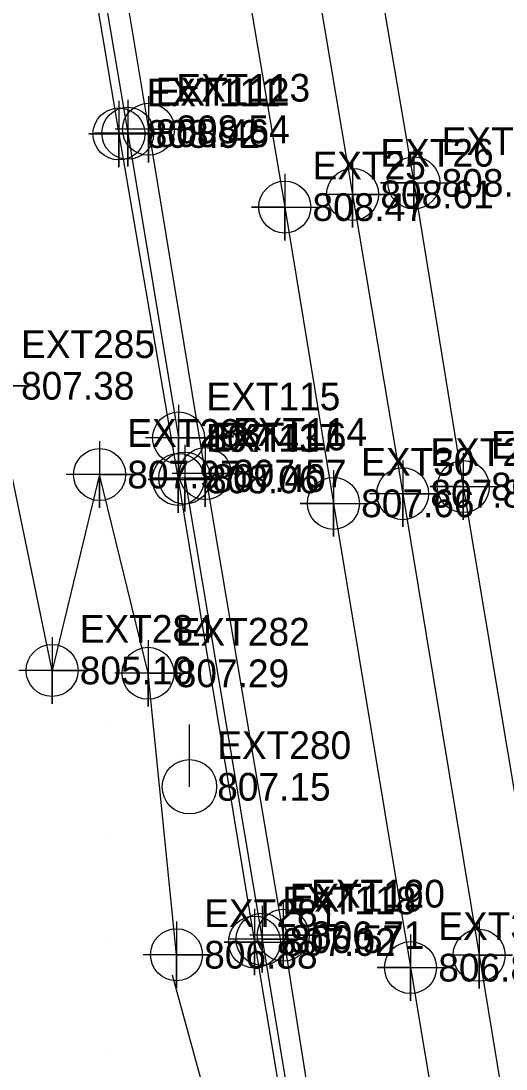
# Model space of a CAD drawing. Extents: x 1762120 to 1766775, y 709485 to 712965.
# Drawn here: x 1763802.3 to 1763846.1, y 712558.7 to 712653.2 of the extents above; entities that cross this region are included whole.
import ezdxf

# ---------------------------------------------------------------- set-up
doc = ezdxf.new("R2010")
doc.units = 0
for name, color, linetype in [('Exist DTM Breakline', 7, 'Continuous'), ('Exist DTM Breakline Cogo Elevation', 7, 'Continuous'), ('Exist DTM Breakline Cogo Number', 7, 'Continuous'), ('Exist DTM Breakline Cogo Point CELL', 7, 'Continuous'), ('Exist DTM Crownline', 7, 'Continuous'), ('Exist DTM Crownline Cogo Elevation', 7, 'Continuous'), ('Exist DTM Crownline Cogo Number', 7, 'Continuous'), ('Exist DTM Crownline Cogo Point CELL', 7, 'Continuous'), ('Exist DTM Drainline', 7, 'Continuous'), ('Exist DTM Drainline Cogo Elevation', 7, 'Continuous'), ('Exist DTM Drainline Cogo Number', 7, 'Continuous'), ('Exist DTM Drainline Cogo Point CELL', 7, 'Continuous'), ('Exist DTM QL2 LIDAR Elevation Point', 7, 'Continuous'), ('Exist Roads Curbs', 7, 'Continuous'), ('Exist Roads Curbs Cogo Elevation', 7, 'Continuous'), ('Exist Roads Curbs Cogo Number', 7, 'Continuous'), ('Exist Roads Curbs Cogo Point CELL', 7, 'Continuous'), ('Exist Roads EOP', 7, 'Continuous'), ('Exist Roads EOP Cogo Elevation', 7, 'Continuous'), ('Exist Roads EOP Cogo Number', 7, 'Continuous'), ('Exist Roads EOP Cogo Point CELL', 7, 'Continuous'), ('Exist Roads EOT', 7, 'Continuous'), ('Exist Roads EOT Cogo Elevation', 7, 'Continuous'), ('Exist Roads EOT Cogo Number', 7, 'Continuous'), ('Exist Roads EOT Cogo Point CELL', 7, 'Continuous'), ('Exist Utilities Power Pole CELL', 7, 'Continuous'), ('Exist Utilities Power Pole Cogo Elevation', 7, 'Continuous'), ('Exist Utilities Power Pole Cogo Number', 7, 'Continuous'), ('PH Exist DTM Breakline', 7, 'Continuous')]:
    doc.layers.add(name, color=color, linetype=linetype)

msp = doc.modelspace()

# ---------------------------------------------------------------- linework, layer by layer
at = {"layer": 'Exist DTM Breakline'}
msp.add_lwpolyline([(1763816.336, 712568.975), (1763813.77, 712594.344), (1763809.401, 712612.263), (1763805.117, 712594.603), (1763799.817, 712620.266), (1763789.401, 712652.954), (1763785.334, 712685.719)], dxfattribs=at)
at = {"layer": 'Exist DTM Breakline Cogo Point CELL'}
for points in [[(1763799.817, 712623.266), (1763799.817, 712617.266), (1763799.817, 712620.266), (1763802.817, 712620.266), (1763796.817, 712620.266)], [(1763809.401, 712615.263), (1763809.401, 712609.263), (1763809.401, 712612.263), (1763812.401, 712612.263), (1763806.401, 712612.263)], [(1763805.117, 712597.603), (1763805.117, 712591.603), (1763805.117, 712594.603), (1763808.117, 712594.603), (1763802.117, 712594.603)], [(1763813.77, 712597.344), (1763813.77, 712591.344), (1763813.77, 712594.344), (1763816.77, 712594.344), (1763810.77, 712594.344)], [(1763816.336, 712571.975), (1763816.336, 712565.975), (1763816.336, 712568.975), (1763819.336, 712568.975), (1763813.336, 712568.975)]]:
    msp.add_lwpolyline(points, dxfattribs=at)
for centre in [(1763809.401, 712612.263), (1763805.117, 712594.603), (1763813.77, 712594.344), (1763816.336, 712568.975)]:
    msp.add_circle(centre, 2.344, dxfattribs=at)
at = {"layer": 'Exist DTM Crownline'}
msp.add_line((1763843.626, 712568.925), (1763848.874, 712537.033), dxfattribs=at)
msp.add_lwpolyline([(1763783.92, 712926.058), (1763790.262, 712887.319), (1763795.183, 712859.532), (1763803.032, 712808.629), (1763808.926, 712776.275), (1763814.523, 712743.371), (1763820.27, 712708.85), (1763825.749, 712675.916), (1763832.222, 712637.522), (1763836.733, 712610.54), (1763843.626, 712568.925)], dxfattribs=at)
at = {"layer": 'Exist DTM Crownline Cogo Point CELL'}
for points in [[(1763832.222, 712640.522), (1763832.222, 712634.522), (1763832.222, 712637.522), (1763835.222, 712637.522), (1763829.222, 712637.522)], [(1763836.733, 712613.54), (1763836.733, 712607.54), (1763836.733, 712610.54), (1763839.733, 712610.54), (1763833.733, 712610.54)], [(1763843.626, 712571.925), (1763843.626, 712565.925), (1763843.626, 712568.925), (1763846.626, 712568.925), (1763840.626, 712568.925)]]:
    msp.add_lwpolyline(points, dxfattribs=at)
for centre in [(1763832.222, 712637.522), (1763836.733, 712610.54), (1763843.626, 712568.925)]:
    msp.add_circle(centre, 2.344, dxfattribs=at)
at = {"layer": 'Exist DTM Drainline'}
msp.add_line((1763817.077, 712611.946), (1763824.048, 712570.37), dxfattribs=at)
for points in [[(1763781.288, 712825.282), (1763786.304, 712795.661), (1763793.687, 712751.498), (1763799.331, 712717.754), (1763805.438, 712681.563), (1763811.952, 712643.035), (1763816.532, 712615.56)], [(1763824.048, 712570.37), (1763827.225, 712551.256), (1763833.688, 712512.933), (1763834.31, 712508.288)]]:
    msp.add_lwpolyline(points, dxfattribs=at)
at = {"layer": 'Exist DTM Drainline Cogo Point CELL'}
for points in [[(1763811.952, 712646.035), (1763811.952, 712640.035), (1763811.952, 712643.035), (1763814.952, 712643.035), (1763808.952, 712643.035)], [(1763816.532, 712618.56), (1763816.532, 712612.56), (1763816.532, 712615.56), (1763819.532, 712615.56), (1763813.532, 712615.56)], [(1763817.077, 712614.946), (1763817.077, 712608.946), (1763817.077, 712611.946), (1763820.077, 712611.946), (1763814.077, 712611.946)], [(1763824.048, 712573.37), (1763824.048, 712567.37), (1763824.048, 712570.37), (1763827.048, 712570.37), (1763821.048, 712570.37)]]:
    msp.add_lwpolyline(points, dxfattribs=at)
for centre in [(1763811.952, 712643.035), (1763816.532, 712615.56), (1763817.077, 712611.946), (1763824.048, 712570.37)]:
    msp.add_circle(centre, 2.344, dxfattribs=at)
at = {"layer": 'Exist DTM QL2 LIDAR Elevation Point'}
for p, q in [((1763810, 712620), (1763810, 712620)), ((1763810, 712590), (1763810, 712590)), ((1763810, 712580), (1763810, 712580)), ((1763810, 712570), (1763810, 712570)), ((1763810, 712560), (1763810, 712560))]:
    msp.add_line(p, q, dxfattribs=at)
at = {"layer": 'Exist Roads Curbs'}
for points in [[(1763764.468, 712921.993), (1763771.224, 712881.371), (1763777.799, 712842.52), (1763785.017, 712799.156), (1763793.002, 712751.297), (1763798.517, 712717.85), (1763798.751, 712716.41), (1763801.856, 712697.916), (1763802.154, 712696.936), (1763804.688, 712681.498), (1763811.149, 712642.967), (1763816.501, 712611.824), (1763823.372, 712570.121)], [(1763823.372, 712570.121), (1763826.523, 712551.26), (1763832.916, 712512.967), (1763833.683, 712508.175)]]:
    msp.add_lwpolyline(points, dxfattribs=at)
at = {"layer": 'Exist Roads Curbs Cogo Point CELL'}
for points in [[(1763811.149, 712645.967), (1763811.149, 712639.967), (1763811.149, 712642.967), (1763808.419, 712642.967), (1763814.149, 712642.967)], [(1763816.501, 712614.824), (1763816.501, 712608.824), (1763816.501, 712611.824), (1763813.771, 712611.824), (1763819.501, 712611.824)], [(1763823.372, 712573.121), (1763823.372, 712567.121), (1763823.372, 712570.121), (1763820.642, 712570.121), (1763826.372, 712570.121)]]:
    msp.add_lwpolyline(points, dxfattribs=at)
for centre in [(1763811.149, 712642.967), (1763816.501, 712611.824), (1763823.372, 712570.121)]:
    msp.add_circle(centre, 2.344, dxfattribs=at)
at = {"layer": 'Exist Roads EOP'}
for points in [[(1763767.083, 712922.223), (1763773.823, 712881.974), (1763780.335, 712842.895), (1763788.848, 712791.154), (1763795.539, 712751.806), (1763801.2, 712718.139), (1763807.385, 712682.013), (1763813.812, 712643.387), (1763818.936, 712612.35), (1763825.965, 712570.729)], [(1763825.965, 712570.729), (1763828.989, 712551.557), (1763835.435, 712513.335), (1763836.189, 712508.687)]]:
    msp.add_lwpolyline(points, dxfattribs=at)
at = {"layer": 'Exist Roads EOP Cogo Point CELL'}
for points in [[(1763813.812, 712646.387), (1763813.812, 712640.387), (1763813.812, 712643.387), (1763816.812, 712643.387), (1763810.812, 712643.387)], [(1763818.936, 712615.35), (1763818.936, 712609.35), (1763818.936, 712612.35), (1763821.936, 712612.35), (1763815.936, 712612.35)], [(1763825.965, 712573.729), (1763825.965, 712567.729), (1763825.965, 712570.729), (1763828.965, 712570.729), (1763822.965, 712570.729)]]:
    msp.add_lwpolyline(points, dxfattribs=at)
for centre in [(1763813.812, 712643.387), (1763818.936, 712612.35), (1763825.965, 712570.729)]:
    msp.add_circle(centre, 2.344, dxfattribs=at)
at = {"layer": 'Exist Roads EOT'}
for points in [[(1763789.832, 712926.884), (1763795.992, 712888.052), (1763800.75, 712859.942), (1763807.254, 712820.955), (1763816.86, 712762.721), (1763822.148, 712731.849), (1763825.695, 712709.767), (1763831.213, 712676.817), (1763837.744, 712638.56), (1763842.2, 712611.183), (1763849.139, 712569.759)], [(1763777.488, 712924.55), (1763781.487, 712903.204), (1763789.164, 712854.697), (1763797.205, 712808.308), (1763802.541, 712775.258), (1763808.303, 712742.168), (1763814.095, 712707.894), (1763819.559, 712674.99), (1763826.1, 712636.377), (1763830.485, 712609.669), (1763837.441, 712567.81)], [(1763837.441, 712567.81), (1763842.568, 712537.12), (1763847.598, 712508.586)]]:
    msp.add_lwpolyline(points, dxfattribs=at)
at = {"layer": 'Exist Roads EOT Cogo Point CELL'}
for points in [[(1763837.744, 712641.56), (1763837.744, 712635.56), (1763837.744, 712638.56), (1763834.744, 712638.56), (1763840.744, 712638.56)], [(1763826.1, 712639.377), (1763826.1, 712633.377), (1763826.1, 712636.377), (1763823.1, 712636.377), (1763829.1, 712636.377)], [(1763842.2, 712614.183), (1763842.2, 712608.183), (1763842.2, 712611.183), (1763839.2, 712611.183), (1763845.2, 712611.183)], [(1763830.485, 712612.669), (1763830.485, 712606.669), (1763830.485, 712609.669), (1763827.485, 712609.669), (1763833.485, 712609.669)], [(1763837.441, 712570.81), (1763837.441, 712564.81), (1763837.441, 712567.81), (1763834.441, 712567.81), (1763840.441, 712567.81)]]:
    msp.add_lwpolyline(points, dxfattribs=at)
for centre in [(1763837.744, 712638.56), (1763826.1, 712636.377), (1763842.2, 712611.183), (1763830.485, 712609.669), (1763837.441, 712567.81)]:
    msp.add_circle(centre, 2.344, dxfattribs=at)
at = {"layer": 'Exist Utilities Power Pole CELL'}
for q in [(1763817.508, 712589.739), (1763817.508, 712584.114)]:
    msp.add_line((1763817.508, 712584.114), q, dxfattribs=at)
msp.add_circle((1763817.508, 712584.114), 2.45, dxfattribs=at)
at = {"layer": 'PH Exist DTM Breakline'}
msp.add_lwpolyline([(1763815.936, 712567.159), (1763818.702, 712557.056), (1763819.598, 712547.204), (1763818.168, 712532.899), (1763817.792, 712521.914), (1763824.247, 712505.477), (1763832.242, 712481.102)], dxfattribs=at)

# ---------------------------------------------------------------- texts
at = {"layer": 'Exist DTM Breakline Cogo Elevation'}
for s, p in [('807.38', (1763802.317, 712619.016)), ('807.97', (1763811.901, 712611.013)), ('805.10', (1763807.617, 712593.353)), ('807.29', (1763816.27, 712593.094)), ('806.88', (1763818.836, 712567.725))]:
    msp.add_text(s, height=2.5, dxfattribs=at).set_placement(p)
at = {"layer": 'Exist DTM Breakline Cogo Number'}
for s, p in [('EXT285', (1763802.317, 712622.766)), ('EXT283', (1763811.901, 712614.763)), ('EXT284', (1763807.617, 712597.103)), ('EXT282', (1763816.27, 712596.844)), ('EXT281', (1763818.836, 712571.475))]:
    msp.add_text(s, height=2.5, dxfattribs=at).set_placement(p)
at = {"layer": 'Exist DTM Crownline Cogo Elevation'}
for s, p in [('808.61', (1763834.722, 712636.272)), ('807.82', (1763839.233, 712609.29))]:
    msp.add_text(s, height=2.5, dxfattribs=at).set_placement(p)
at = {"layer": 'Exist DTM Crownline Cogo Number'}
for s, p in [('EXT26', (1763834.722, 712640.022)), ('EXT29', (1763839.233, 712613.04))]:
    msp.add_text(s, height=2.5, dxfattribs=at).set_placement(p)
at = {"layer": 'Exist DTM Drainline Cogo Elevation'}
for s, p in [('808.46', (1763814.452, 712641.785)), ('807.43', (1763819.032, 712614.31)), ('807.40', (1763819.577, 712610.696)), ('806.57', (1763826.548, 712569.12))]:
    msp.add_text(s, height=2.5, dxfattribs=at).set_placement(p)
at = {"layer": 'Exist DTM Drainline Cogo Number'}
for s, p in [('EXT112', (1763814.452, 712645.535)), ('EXT115', (1763819.032, 712618.06)), ('EXT116', (1763819.577, 712614.446)), ('EXT119', (1763826.548, 712572.87))]:
    msp.add_text(s, height=2.5, dxfattribs=at).set_placement(p)
at = {"layer": 'Exist Roads Curbs Cogo Elevation'}
for s, p in [('808.92', (1763813.649, 712641.717)), ('808.06', (1763819.001, 712610.574)), ('807.02', (1763825.872, 712568.871))]:
    msp.add_text(s, height=2.5, dxfattribs=at).set_placement(p)
at = {"layer": 'Exist Roads Curbs Cogo Number'}
for s, p in [('EXT111', (1763813.649, 712645.467)), ('EXT117', (1763819.001, 712614.324)), ('EXT118', (1763825.872, 712572.621))]:
    msp.add_text(s, height=2.5, dxfattribs=at).set_placement(p)
at = {"layer": 'Exist Roads EOP Cogo Elevation'}
for s, p in [('808.54', (1763816.312, 712642.137)), ('807.57', (1763821.436, 712611.1)), ('806.71', (1763828.465, 712569.479))]:
    msp.add_text(s, height=2.5, dxfattribs=at).set_placement(p)
at = {"layer": 'Exist Roads EOP Cogo Number'}
for s, p in [('EXT113', (1763816.312, 712645.887)), ('EXT114', (1763821.436, 712614.85)), ('EXT120', (1763828.465, 712573.229))]:
    msp.add_text(s, height=2.5, dxfattribs=at).set_placement(p)
at = {"layer": 'Exist Roads EOT Cogo Elevation'}
for s, p in [('808.55', (1763840.244, 712637.31)), ('808.47', (1763828.6, 712635.127)), ('807.72', (1763844.7, 712609.933)), ('807.66', (1763832.985, 712608.419)), ('806.87', (1763839.941, 712566.56))]:
    msp.add_text(s, height=2.5, dxfattribs=at).set_placement(p)
at = {"layer": 'Exist Roads EOT Cogo Number'}
for s, p in [('EXT27', (1763840.244, 712641.06)), ('EXT25', (1763828.6, 712638.877)), ('EXT28', (1763844.7, 712613.683)), ('EXT30', (1763832.985, 712612.169)), ('EXT31', (1763839.941, 712570.31))]:
    msp.add_text(s, height=2.5, dxfattribs=at).set_placement(p)
at = {"layer": 'Exist Utilities Power Pole Cogo Elevation'}
msp.add_text('807.15', height=2.5, dxfattribs=at).set_placement((1763820.008, 712582.864))
at = {"layer": 'Exist Utilities Power Pole Cogo Number'}
msp.add_text('EXT280', height=2.5, dxfattribs=at).set_placement((1763820.008, 712586.614))

doc.saveas('drawing.dxf')
